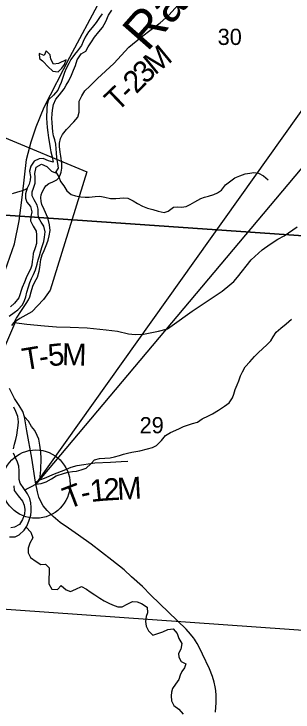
# Model space of a CAD drawing. Extents: x 0 to 34, y 0 to 22.
# Drawn here: x 27.834 to 28.554, y 16.59 to 18.393 of the extents above; entities that cross this region are included whole.
import ezdxf

# ---------------------------------------------------------------- set-up
doc = ezdxf.new("R2010")
doc.units = 0
for name, color, linetype in [('GM_X_Corporation', 7, 'Continuous'), ('GM_X_Major_River', 7, 'Continuous'), ('GM_X_Major_River_Text', 7, 'Continuous'), ('GM_X_Minor_Lake', 7, 'Continuous'), ('GM_X_Minor_River', 7, 'Continuous'), ('GM_X_Rail_Line', 7, 'Continuous'), ('GM_X_Section', 7, 'Continuous'), ('GM_X_Section_Text', 7, 'Continuous'), ('GM_X_State_Route', 7, 'Continuous'), ('GM_X_Township_Road', 7, 'Continuous'), ('GM_X_Township_Road_Text', 7, 'Continuous'), ('SH_Data', 7, 'Continuous')]:
    doc.layers.add(name, color=color, linetype=linetype)

msp = doc.modelspace()

# ---------------------------------------------------------------- linework, layer by layer
at = {"layer": 'GM_X_Corporation'}
msp.add_lwpolyline([(27.6365, 17.1274), (27.4226, 17.2144), (27.4242, 17.2466), (27.3779, 17.2466), (27.3482, 17.2539), (27.433, 17.4716), (27.2534, 17.5487), (27.314, 17.6957), (27.362, 17.6745), (27.5761, 18.1708), (28.0217, 17.9852), (27.9273, 17.6794), (27.9105, 17.6553), (27.8801, 17.6232), (27.8492, 17.6058), (27.8383, 17.5985)], close=True, dxfattribs=at)
at = {"layer": 'GM_X_Major_River'}
for points in [[(27.8221, 17.612), (27.8346, 17.6214), (27.8442, 17.6289), (27.856, 17.6417), (27.8614, 17.6527), (27.8645, 17.6625), (27.8672, 17.6742), (27.8719, 17.6882), (27.8754, 17.6988), (27.8796, 17.7091), (27.8846, 17.72), (27.89, 17.7321), (27.8943, 17.7465), (27.897, 17.7579), (27.9001, 17.7681), (27.9032, 17.781), (27.9071, 17.7923), (27.911, 17.8048), (27.9125, 17.8162), (27.9149, 17.8298), (27.9112, 17.8443), (27.9045, 17.8546), (27.8973, 17.8671), (27.897, 17.8774), (27.8963, 17.8884), (27.8937, 17.8987), (27.8859, 17.9128), (27.881, 17.9227), (27.8807, 17.9329), (27.8846, 17.9427), (27.8892, 17.956), (27.8889, 17.9708), (27.8878, 17.9803), (27.8917, 17.9966), (27.9051, 18.0048), (27.9187, 17.9986), (27.9311, 17.9868), (27.9413, 17.9825), (27.949, 17.9946), (27.9476, 18.0064), (27.945, 18.0208), (27.9439, 18.0337), (27.9429, 18.0447), (27.9418, 18.0565), (27.9392, 18.0675), (27.9363, 18.0782), (27.9344, 18.0881), (27.9334, 18.0995), (27.9323, 18.1124), (27.932, 18.1226), (27.9325, 18.1344), (27.9333, 18.1446), (27.9357, 18.1586), (27.9422, 18.1722), (27.9514, 18.1839), (27.9632, 18.1994), (27.969, 18.2092), (27.9759, 18.2198), (27.9821, 18.2349), (27.9875, 18.2474), (27.9925, 18.2599), (27.9971, 18.2746), (28.0075, 18.2897), (28.0196, 18.2965), (28.0258, 18.3078), (28.0338, 18.3207), (28.0419, 18.3324), (28.053, 18.3463), (28.0622, 18.3573), (28.071, 18.3731), (28.0779, 18.3894), (28.0867, 18.4026)], [(28.0613, 18.3933), (28.0547, 18.3835), (28.0463, 18.3707), (28.0356, 18.3578), (28.0264, 18.3465), (28.018, 18.3329), (28.0126, 18.3212), (28.0084, 18.311), (27.9984, 18.2974), (27.99, 18.2876), (27.9808, 18.2748), (27.9754, 18.2649), (27.9689, 18.2517), (27.9647, 18.2415), (27.96, 18.229), (27.9558, 18.2158), (27.9515, 18.2059), (27.9469, 18.1957), (27.9362, 18.1829), (27.9236, 18.1705), (27.9201, 18.1599), (27.9185, 18.1489), (27.9184, 18.1235), (27.9191, 18.1117), (27.9201, 18.0996), (27.9212, 18.0866), (27.923, 18.0726), (27.9255, 18.0578), (27.9273, 18.0468), (27.9292, 18.0369), (27.9325, 18.024), (27.9354, 18.0103), (27.923, 18.0134), (27.9097, 18.0192), (27.8991, 18.0189), (27.8865, 18.0125), (27.8773, 17.9997), (27.8746, 17.9864), (27.8764, 17.9731), (27.876, 17.9637), (27.8732, 17.9531), (27.8682, 17.9425), (27.864, 17.9281), (27.8643, 17.9167), (27.8672, 17.9068), (27.8767, 17.895), (27.88, 17.8813), (27.8776, 17.8699), (27.8772, 17.8582), (27.8839, 17.8445), (27.891, 17.8315), (27.8921, 17.822), (27.8924, 17.8125), (27.892, 17.7996), (27.8889, 17.789), (27.8838, 17.7743), (27.8826, 17.7633), (27.8814, 17.7534), (27.8802, 17.744), (27.8771, 17.7337), (27.8717, 17.7239), (27.866, 17.711), (27.861, 17.7001), (27.8556, 17.6861), (27.847, 17.6596), (27.8356, 17.646), (27.8253, 17.6366)], [(27.8327, 17.2693), (27.8358, 17.2818), (27.8386, 17.2939), (27.8413, 17.3052), (27.8433, 17.3178), (27.8452, 17.3295), (27.8457, 17.3394), (27.8439, 17.353), (27.8394, 17.3656), (27.8334, 17.3774)], [(27.8229, 17.0421), (27.8373, 17.0427), (27.8472, 17.0476), (27.8609, 17.0596), (27.867, 17.0698), (27.8728, 17.0831), (27.8775, 17.0982), (27.8787, 17.1081), (27.8787, 17.1179), (27.8773, 17.1297), (27.8747, 17.1411), (27.8691, 17.1533), (27.8593, 17.167), (27.8499, 17.1807), (27.8477, 17.1906), (27.8479, 17.213), (27.8464, 17.2248), (27.8435, 17.235), (27.8394, 17.2446), (27.8326, 17.2583)], [(27.834, 17.174), (27.835, 17.1619), (27.8452, 17.1478), (27.8561, 17.1348), (27.8609, 17.1241), (27.8624, 17.1131), (27.8612, 17.1006), (27.8558, 17.087), (27.8485, 17.0741), (27.8359, 17.067), (27.826, 17.0652)]]:
    msp.add_lwpolyline(points, dxfattribs=at)
at = {"layer": 'GM_X_Minor_Lake'}
for points in [[(27.969, 18.2745), (27.9489, 18.265), (27.9357, 18.2634), (27.9296, 18.2755), (27.9273, 18.2869), (27.917, 18.2971), (27.9121, 18.285), (27.8992, 18.2903), (27.8997, 18.2777), (27.9075, 18.2713)], [(27.9075, 18.2713), (27.9107, 18.2687), (27.9213, 18.2566), (27.9342, 18.2452), (27.9479, 18.2434), (27.9577, 18.2525), (27.9641, 18.2624), (27.969, 18.2745)]]:
    msp.add_lwpolyline(points, dxfattribs=at)
at = {"layer": 'GM_X_Minor_River'}
for points in [[(27.9425, 17.9844), (27.9495, 17.9719), (27.9541, 17.9597), (27.9624, 17.9484), (27.9704, 17.9359), (27.9814, 17.9261), (27.9928, 17.9227), (28.0068, 17.9204), (28.0174, 17.9193), (28.0284, 17.9193), (28.0435, 17.9209), (28.056, 17.9217), (28.0689, 17.9191), (28.0829, 17.9161), (28.0969, 17.9161), (28.1068, 17.9169), (28.1177, 17.9181), (28.128, 17.9169), (28.1416, 17.9098), (28.153, 17.9033), (28.1659, 17.8966), (28.1784, 17.8909), (28.192, 17.8879), (28.2057, 17.883), (28.2212, 17.8796), (28.2322, 17.8831), (28.2454, 17.8933), (28.256, 17.8949), (28.2666, 17.8934), (28.2779, 17.8953), (28.2881, 17.901), (28.3006, 17.9071), (28.3157, 17.9159), (28.3256, 17.9193), (28.3354, 17.9224), (28.3494, 17.9262), (28.3592, 17.9304), (28.3694, 17.9376), (28.3796, 17.9513), (28.3902, 17.9593), (28.4034, 17.9696), (28.417, 17.9745), (28.4302, 17.9795), (28.4423, 17.9814), (28.4525, 17.9833), (28.4647, 17.9818), (28.4775, 17.9743), (28.4893, 17.9641)], [(27.868, 17.9415), (27.8648, 17.939), (27.8531, 17.9348), (27.8429, 17.9325), (27.8293, 17.928)], [(27.8621, 17.1632), (27.8654, 17.1651), (27.879, 17.1723), (27.8907, 17.1784), (27.9047, 17.1804), (27.9176, 17.1846), (27.9308, 17.1918), (27.9433, 17.1994), (27.9645, 17.2071), (27.9743, 17.2094), (27.9853, 17.2109), (27.9951, 17.2117), (28.0076, 17.2151), (28.0201, 17.2197), (28.0325, 17.2304), (28.042, 17.241), (28.0548, 17.2444), (28.0684, 17.2456), (28.0824, 17.2464), (28.0938, 17.2491), (28.1059, 17.2521), (28.1165, 17.2556), (28.1267, 17.2583), (28.1384, 17.2613), (28.1483, 17.2629), (28.1585, 17.2648), (28.1789, 17.2694), (28.191, 17.2732), (28.202, 17.2778), (28.2144, 17.2911), (28.2253, 17.304), (28.2378, 17.3116), (28.2514, 17.3181), (28.2612, 17.3223), (28.2711, 17.3269), (28.2813, 17.3307), (28.2945, 17.3353), (28.3074, 17.3387), (28.3198, 17.3467), (28.3361, 17.3551), (28.3459, 17.3597), (28.3614, 17.3692), (28.3769, 17.3798), (28.389, 17.3882), (28.3973, 17.4011), (28.4014, 17.4106), (28.4044, 17.4224), (28.4097, 17.4345), (28.4138, 17.4448), (28.4179, 17.4581), (28.4232, 17.4687), (28.4303, 17.4816), (28.442, 17.4945), (28.4541, 17.5078), (28.4643, 17.5185), (28.4862, 17.5382), (28.4963, 17.5489), (28.5027, 17.5591), (28.5107, 17.5709), (28.5224, 17.5812), (28.5359, 17.5922), (28.5495, 17.6044)], [(27.8653, 17.0669), (27.8775, 17.0544), (27.8825, 17.04), (27.875, 17.026), (27.8705, 17.0131), (27.8705, 17.0009), (27.8766, 16.9888), (27.8914, 16.9782), (27.9035, 16.9707), (27.9156, 16.9718), (27.9248, 16.962), (27.9248, 16.9495), (27.9241, 16.9351), (27.9245, 16.9207), (27.9321, 16.9074), (27.9461, 16.9063), (27.9563, 16.9169), (27.9689, 16.9056), (27.9802, 16.9015), (27.9938, 16.9068), (28.0082, 16.9137), (28.0211, 16.9069), (28.0306, 16.9001), (28.0431, 16.8921), (28.056, 16.8842), (28.0666, 16.8766), (28.0784, 16.871), (28.0882, 16.8665), (28.1019, 16.8612), (28.1128, 16.8616), (28.1265, 16.8688), (28.1401, 16.8749), (28.1522, 16.8742), (28.1628, 16.8704), (28.178, 16.8606), (28.1788, 16.8458), (28.1754, 16.8363), (28.1732, 16.8238), (28.1747, 16.8113), (28.1808, 16.7996), (28.1926, 16.7882), (28.2051, 16.7924), (28.2179, 16.797), (28.2311, 16.8027), (28.2444, 16.805), (28.2546, 16.7925), (28.2596, 16.7797), (28.2668, 16.7664), (28.2646, 16.7524), (28.2582, 16.7406), (28.2594, 16.7311), (28.2655, 16.7201), (28.2772, 16.7141), (28.2742, 16.7042), (28.2671, 16.6944), (28.2629, 16.6849), (28.2592, 16.6742), (28.2509, 16.6617), (28.243, 16.6507), (28.2408, 16.6412), (28.2393, 16.6313), (28.2408, 16.6184), (28.2465, 16.6063), (28.2594, 16.5973), (28.2708, 16.5844)]]:
    msp.add_lwpolyline(points, dxfattribs=at)
at = {"layer": 'GM_X_Rail_Line'}
msp.add_lwpolyline([(26.5786, 16.733), (26.6481, 16.7486), (26.8176, 16.7869), (27.0402, 16.8315), (27.1711, 16.8577), (27.2441, 16.875), (27.3175, 16.9041), (27.3875, 16.9452), (27.438, 16.9856), (27.4932, 17.0339), (27.5486, 17.1099), (27.5938, 17.1974), (27.7498, 17.5842), (27.8117, 17.7304), (27.8358, 17.7987), (27.8472, 17.8588), (27.856, 17.9255), (27.8667, 18.0165), (27.8787, 18.0627), (27.8912, 18.1011), (27.9122, 18.1517), (27.978, 18.2807), (28.2126, 18.7214)], dxfattribs=at)
at = {"layer": 'GM_X_Section'}
msp.add_lwpolyline([(28.7433, 18.1795), (28.7165, 17.8103), (27.7492, 17.8771), (27.8204, 18.905), (28.7909, 18.8364), (28.7636, 18.4595)], dxfattribs=at)
msp.add_lwpolyline([(27.7492, 17.8771), (28.7165, 17.8103), (28.6406, 16.7957), (27.6556, 16.8655)], close=True, dxfattribs=at)
at = {"layer": 'GM_X_State_Route'}
msp.add_lwpolyline([(28.3541, 16.5891), (28.3558, 16.6145), (28.3556, 16.6324), (28.3543, 16.6451), (28.3531, 16.655), (28.3507, 16.6666), (28.3459, 16.6816), (28.3383, 16.7013), (28.3205, 16.7393), (28.3115, 16.7573), (28.3066, 16.7666), (28.3024, 16.7735), (28.2994, 16.778), (28.2967, 16.7814), (28.2891, 16.7906), (28.2779, 16.8035), (28.1868, 16.892), (28.1653, 16.9136), (28.1376, 16.9394), (28.1182, 16.9573), (28.0865, 16.9822), (28.0333, 17.0234), (28.0009, 17.0467), (27.975, 17.0646), (27.9532, 17.0796), (27.9355, 17.0944), (27.92, 17.11), (27.9097, 17.1227), (27.9031, 17.1333), (27.8981, 17.1449), (27.8945, 17.1582), (27.8896, 17.1837), (27.8803, 17.2454), (27.8677, 17.3162), (27.8616, 17.3519), (27.8567, 17.3658), (27.8472, 17.3814), (27.8356, 17.3998), (27.8224, 17.4253)], dxfattribs=at)
at = {"layer": 'GM_X_Township_Road'}
for points in [[(27.8346, 17.5959), (27.8405, 17.6073), (27.8534, 17.6269), (27.8653, 17.6452), (27.8718, 17.6541), (27.8755, 17.6623), (27.8785, 17.6754), (27.8829, 17.6898), (27.8884, 17.7012), (27.8948, 17.7131), (27.8993, 17.728), (27.9005, 17.7377), (27.9035, 17.7585), (27.907, 17.7709), (27.9117, 17.7814), (27.9189, 17.7989), (27.9221, 17.8086), (27.9248, 17.8197), (27.9271, 17.8336), (27.9261, 17.848), (27.9214, 17.8661), (27.9117, 17.8879), (27.906, 17.9003), (27.9042, 17.908), (27.9033, 17.9189), (27.9047, 17.9256), (27.907, 17.9322), (27.9117, 17.9419), (27.9161, 17.9486), (27.9241, 17.9549), (27.934, 17.959), (27.9444, 17.964), (27.9494, 17.9687), (27.9536, 17.9764), (27.9561, 17.9845), (27.9575, 17.994), (27.9575, 18.0069), (27.9548, 18.0257), (27.9531, 18.0356), (27.9516, 18.05), (27.9516, 18.0587), (27.9541, 18.0713), (27.9593, 18.0815), (27.9699, 18.0941), (27.9885, 18.1137), (27.9989, 18.1263), (28.0019, 18.1392), (28.0019, 18.1558), (28.002, 18.1677), (28.0088, 18.1816), (28.0166, 18.1941), (28.0297, 18.2063), (28.0495, 18.2258), (28.0914, 18.2648), (28.1306, 18.3068), (28.1634, 18.3333), (28.1881, 18.3523), (28.2109, 18.3696), (28.2335, 18.3895), (28.2575, 18.4159)], [(27.8284, 17.5884), (27.8346, 17.5959), (27.8673, 17.5917), (27.9132, 17.5874), (27.9442, 17.585), (27.9789, 17.5837), (28.023, 17.582), (28.0718, 17.5773), (28.1008, 17.5733), (28.1291, 17.5664), (28.1469, 17.5649), (28.1682, 17.566), (28.2069, 17.5738), (28.2297, 17.5793), (28.242, 17.5877), (28.2934, 17.6249), (28.3714, 17.6771), (28.3906, 17.6928), (28.4008, 17.702), (28.4102, 17.7126), (28.4456, 17.7573), (28.4742, 17.7833), (28.495, 17.7984), (28.5148, 17.811), (28.5306, 17.8196), (28.5641, 17.8427)], [(27.901, 17.1895), (27.9034, 17.2152), (27.9046, 17.2444), (27.9038, 17.2609), (27.901, 17.2794), (27.8981, 17.2949), (27.8941, 17.3044), (27.8877, 17.3166), (27.8797, 17.3276), (27.8719, 17.3413), (27.8616, 17.3519)], [(27.8896, 17.1837), (27.901, 17.1895), (27.9127, 17.1939), (27.9386, 17.2053), (27.9638, 17.2146), (27.9817, 17.222), (27.9974, 17.2264), (28.043, 17.2332), (28.0829, 17.2355), (28.1102, 17.2366), (28.1279, 17.2374)]]:
    msp.add_lwpolyline(points, dxfattribs=at)
at = {"layer": 'SH_Data'}
msp.add_lwpolyline([(27.8907, 17.1784), (28.6022, 18.1795), (28.7314, 18.1795), (27.8907, 17.1784)], close=True, dxfattribs=at)
msp.add_circle((27.8907, 17.1784), 0.0883, dxfattribs=at)

# ---------------------------------------------------------------- texts
at = {"layer": 'GM_X_Major_River_Text'}
msp.add_text('Rac', height=0.0947, rotation=48.5724, dxfattribs=at).set_placement((28.1778, 18.2931))
at = {"layer": 'GM_X_Section_Text'}
for s, p in [('30', (28.3594, 18.3126)), ('29', (28.1582, 17.3097))]:
    msp.add_text(s, height=0.04186, rotation=0, dxfattribs=at).set_placement(p)
at = {"layer": 'GM_X_Township_Road_Text'}
for s, rotation, p in [('M', 39.4168, (28.1977, 18.2333)), ('3', 45.0993, (28.1741, 18.2095)), ('2', 45.1519, (28.1495, 18.1847)), ('T', 43.7726, (28.1009, 18.138)), ('-', 44.0347, (28.1318, 18.1676)), ('5', 5.9747, (27.9246, 17.4824)), ('M', 358.4315, (27.9574, 17.4859)), ('T', 9.3848, (27.8604, 17.4721)), ('-', 8.5794, (27.9022, 17.479)), ('T', 20.9252, (27.9739, 17.113)), ('1', 5.6764, (28.0326, 17.1322)), ('2', 3.4264, (28.0668, 17.1356)), ('M', 3.0435, (28.1016, 17.1377)), ('-', 12.23, (28.0115, 17.1275))]:
    msp.add_text(s, height=0.0568, rotation=rotation, dxfattribs=at).set_placement(p)

doc.saveas('drawing.dxf')
